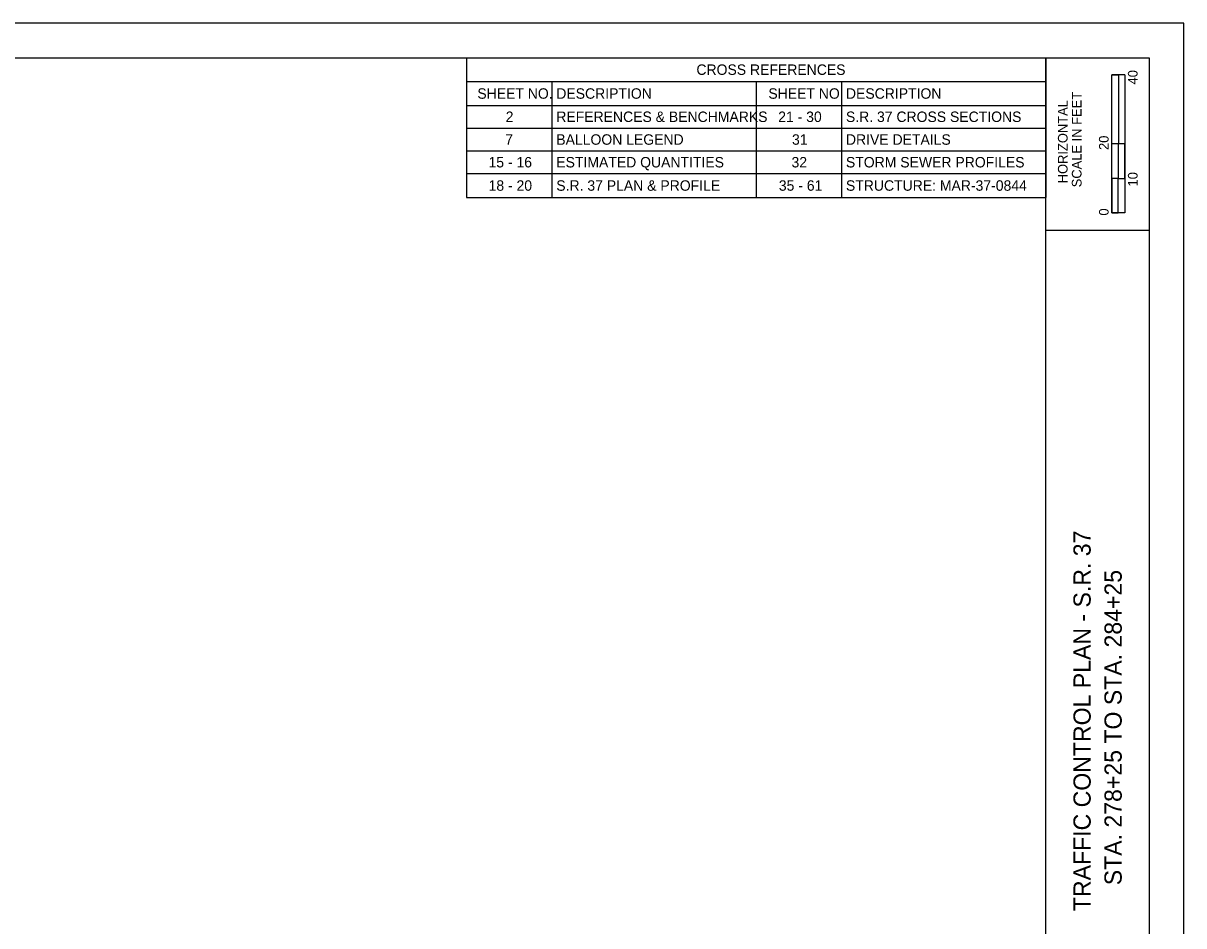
# Model space of a CAD drawing. Extents: x -1.1 to 34, y 0 to 22.
# Drawn here: x 17.17 to 34, y 8.91 to 22 of the extents above; entities that cross this region are included whole.
import ezdxf

# ---------------------------------------------------------------- set-up
doc = ezdxf.new("R2010")
doc.units = 0
for name, color, linetype in [('BR_X_SV_Abut', 7, 'Continuous'), ('CL_X_RW', 7, 'Continuous'), ('RW_X_CL', 7, 'Continuous')]:
    doc.layers.add(name, color=color, linetype=linetype)

msp = doc.modelspace()

# ---------------------------------------------------------------- linework, layer by layer
at = {"layer": 'BR_X_SV_Abut'}
for p, q in [((23.6, 21.5), (32, 21.5)), ((23.6, 21.5), (32, 21.5)), ((23.6, 21.5), (23.6, 19.474)), ((32, 21.5), (32, 19.474)), ((32, 21.5), (32, 19.474)), ((32.957, 19.25), (32.957, 21.25)), ((33.144, 21.25), (32.957, 21.25)), ((32.957, 20.25), (32.957, 21.25)), ((32.957, 21.25), (33.05, 21.25)), ((33.05, 21.25), (33.051, 21.25)), ((33.051, 21.25), (33.051, 20.25)), ((33.144, 21.25), (33.144, 19.25)), ((23.6, 21.154), (32, 21.154)), ((24.835, 21.154), (24.835, 19.474)), ((27.8, 21.154), (27.8, 19.474)), ((29.035, 21.154), (29.035, 19.474)), ((23.6, 20.808), (32, 20.808)), ((23.6, 20.479), (32, 20.479)), ((33.051, 20.25), (32.957, 20.25)), ((33.143, 20.25), (33.05, 20.25)), ((33.05, 20.25), (33.05, 19.75)), ((33.143, 19.75), (33.143, 20.25)), ((23.6, 20.149), (32, 20.149)), ((23.6, 19.82), (32, 19.82)), ((33.05, 19.75), (32.957, 19.75)), ((32.957, 19.75), (32.957, 19.25)), ((33.05, 19.25), (33.05, 19.75)), ((33.05, 19.75), (33.143, 19.75)), ((23.6, 19.474), (32, 19.474)), ((33.144, 19.25), (32.957, 19.25)), ((32.957, 19.25), (33.05, 19.25))]:
    msp.add_line(p, q, dxfattribs=at)
at = {"layer": 'CL_X_RW'}
msp.add_lwpolyline([(0, 0), (34, 0), (34, 22), (0, 22)], close=True, dxfattribs=at)
at = {"layer": 'RW_X_CL'}
for p, q in [((32, 0.5), (32, 21.5)), ((32, 19), (33.5, 19))]:
    msp.add_line(p, q, dxfattribs=at)
msp.add_lwpolyline([(1.5, 21.5), (33.5, 21.5), (33.5, 0.5), (1.5, 0.5)], close=True, dxfattribs=at)

# ---------------------------------------------------------------- texts
at = {"layer": 'BR_X_SV_Abut'}
for s, height, p in [('CROSS REFERENCES', 0.15153, (26.933, 21.251)), ('SHEET NO.', 0.1515, (23.756, 20.905)), ('DESCRIPTION', 0.15153, (24.901, 20.905)), ('SHEET NO', 0.1515, (27.976, 20.905)), ('DESCRIPTION', 0.15153, (29.101, 20.905)), ('2', 0.152, (24.167, 20.568)), ('REFERENCES & BENCHMARKS', 0.15153, (24.901, 20.568)), ('21 - 30', 0.1515, (28.119, 20.568)), ('S.R. 37 CROSS SECTIONS', 0.15153, (29.101, 20.568)), ('7', 0.152, (24.16, 20.238)), ('BALLOON LEGEND', 0.15153, (24.901, 20.238)), ('31', 0.1515, (28.319, 20.238)), ('DRIVE DETAILS', 0.15153, (29.101, 20.238)), ('15 - 16', 0.1515, (23.918, 19.909)), ('ESTIMATED QUANTITIES', 0.15153, (24.901, 19.909)), ('32', 0.1515, (28.312, 19.909)), ('STORM SEWER PROFILES', 0.15153, (29.101, 19.909)), ('18 - 20', 0.1515, (23.919, 19.571)), ('S.R. 37 PLAN & PROFILE', 0.15153, (24.901, 19.571)), ('35 - 61', 0.1515, (28.128, 19.571)), ('STRUCTURE: MAR-37-0844', 0.15153, (29.101, 19.571))]:
    msp.add_text(s, height=height, dxfattribs=at).set_placement(p)
for s, height, p in [('40', 0.14, (33.33, 21.112)), ('HORIZONTAL', 0.14, (32.315, 19.679)), ('SCALE IN FEET', 0.14, (32.517, 19.621)), ('20', 0.14, (32.91, 20.162)), ('10', 0.14, (33.33, 19.633)), ('0', 0.14, (32.91, 19.211)), ('TRAFFIC CONTROL PLAN - S.R. 37', 0.25, (32.65, 9.127)), ('STA. 278+25 TO STA. 284+25', 0.25, (33.1, 9.502))]:
    msp.add_text(s, height=height, rotation=90, dxfattribs=at).set_placement(p)

doc.saveas('drawing.dxf')
